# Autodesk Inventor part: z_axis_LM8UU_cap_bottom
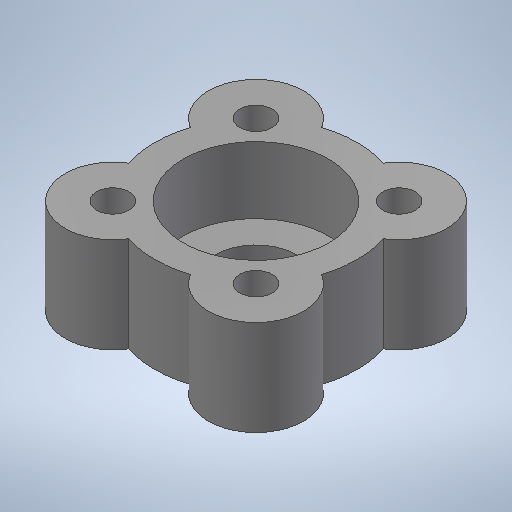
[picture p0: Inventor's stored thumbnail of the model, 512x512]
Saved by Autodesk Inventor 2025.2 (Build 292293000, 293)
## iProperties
Created: 2025-04
Part Number: z_axis_LM8UU_cap_bottom
Material: 1.0037 S235JR
Document SubType Name: Modeling
Designer: BennF
Density: 7.85 g/cm^3
Appearance: Stahl
Author: BennF
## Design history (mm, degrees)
sketch "Sketch2"
  geometry: L1 (0, 0)-(0, -10); L2 (-7.625, 0)-(-7.625, -7); L3 (-7.625, -7)-(-4.25, -7); L4 (-4.25, -7)-(-4.25, -10); L5 (-4.25, -10)-(-10.625, -10); L6 (-10.625, -10)-(-10.625, 0); L7 (-10.625, 0)-(-7.625, 0)
  constraints: 14 end point, 5 perpendicular, 2 horizontal alignment, 2 vertical
  dimensions: "d0" = 15.25 diameter of L2 L1; "d1" = 8.5 diameter of L4 L1; "d2" = 7 distance of L2.start L2.end; "d3" = 3 distance of L3.end L4.end; "d4" = 3 distance between parallel lines of L6 L2
revolve "Revolution1" sketch "Sketch2" stored, may be unused: angle "d5" = 90 deg
sketch "Sketch3"
  geometry: L1 (-7.513, 7.513)-(7.513, -7.513); L2 (7.513, 7.513)-(-7.513, -7.513); A1 r 5 centre (-7.513, 7.513) between (-3.245, 10.117) and (-10.117, 3.245); A2 r 5 centre (7.513, 7.513) between (10.117, 3.245) and (3.245, 10.117); A3 r 5 centre (7.513, -7.513) between (3.245, -10.117) and (10.117, -3.245); A4 r 5 centre (-7.513, -7.513) between (-10.117, -3.245) and (-3.245, -10.117); 3 further points
  constraints: 8 point on circle, 4 centre point, 4 end point, 3 equal radius, 2 midpoint, 1 horizontal alignment, 1 perpendicular, 13 other
  dimensions: "d6" = 5 radius of A1
extrude "Extrusion1" join sketch "Sketch3" stored distance "d7" = 10; taper "d8" = 0 deg
sketch "Sketch4"
  geometry: A1 r 5 centre (-7.513, -7.513) between (-10.117, -3.245) and (-3.245, -10.117) reference; A2 r 5 centre (-7.513, 7.513) between (-3.245, 10.117) and (-10.117, 3.245) reference; A3 r 5 centre (7.513, 7.513) between (10.117, 3.245) and (3.245, 10.117) reference; A4 r 5 centre (7.513, -7.513) between (3.245, -10.117) and (10.117, -3.245) reference; 5 further points
  constraints: 4 coincident
hole "Hole1" sketch "Sketch4" at (-7.513, 7.513), (-7.513, -7.513), (7.513, -7.513), (7.513, 7.513) diameter "d9" = 3.4; stored, may be unused: countersink angle "d13" = 90 deg, drill point angle "d15" = 118 deg; dims "d10" = 6, "d11" = 7.5, "d12" = 2, "d14" = 8
sketch "Sketch5"
  geometry: L1 (-10.413, 9.187)-(-7.513, 10.862); L2 (-7.513, 10.862)-(-4.613, 9.187); L3 (-4.613, 9.187)-(-4.613, 5.839); L4 (-4.613, 5.839)-(-7.513, 4.164); L5 (-7.513, 4.164)-(-10.413, 5.839); L6 (-10.413, 5.839)-(-10.413, 9.187); L7 (7.513, 4.164)-(4.613, 5.839); L8 (4.613, 5.839)-(4.613, 9.187); L9 (4.613, 9.187)-(7.513, 10.862); L10 (7.513, 10.862)-(10.413, 9.187); L11 (10.413, 9.187)-(10.413, 5.839); L12 (10.413, 5.839)-(7.513, 4.164); L13 (7.513, -4.164)-(10.413, -5.839); L14 (10.413, -5.839)-(10.413, -9.187); L15 (10.413, -9.187)-(7.513, -10.862); L16 (7.513, -10.862)-(4.613, -9.187); L17 (4.613, -9.187)-(4.613, -5.839); L18 (4.613, -5.839)-(7.513, -4.164); L19 (-4.613, -5.839)-(-4.613, -9.187); L20 (-4.613, -9.187)-(-7.513, -10.862); L21 (-7.513, -10.862)-(-10.413, -9.187); L22 (-10.413, -9.187)-(-10.413, -5.839); L23 (-10.413, -5.839)-(-7.513, -4.164); L24 (-7.513, -4.164)-(-4.613, -5.839); C1 r 1.7 at (-7.513, 7.513) reference; C2 r 1.7 at (7.513, 7.513) reference; C3 r 1.7 at (7.513, -7.513) reference; C4 r 1.7 at (-7.513, -7.513) reference; 5 further points
  constraints: 48 end point, 4 coincident, 3 parallel, 3 vertical alignment, 1 vertical, 52 other
  dimensions: "d16" = 5.8 distance between parallel lines of L3 L6
extrude "Extrusion2" cut sketch "Sketch5" distance "d17" = 2.5; taper "d18" = 0 deg
body "Solid1"
